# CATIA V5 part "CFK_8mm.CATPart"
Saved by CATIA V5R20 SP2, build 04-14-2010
Part number: CFK_8mm
Bounding box of the stored display mesh (mm): x -4 to 4, y -3.804 to 3.804, z 0 to 200
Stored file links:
  C:\Documents and Settings\Administrator\My Documents\Hobi_dokumenti\CAD_CNC\Clap_CATIA\CFK_8mm.CATPart
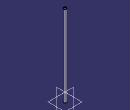
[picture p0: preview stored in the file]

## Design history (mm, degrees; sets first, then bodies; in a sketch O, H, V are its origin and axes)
Body1 (main body)
  Sketch1 on xy-plane, origin (0, 0, 0), H (1, 0, 0), V (0, 1, 0)
    circle A1 centre (0, 0) radius 3
    circle A2 centre (0, 0) radius 4
    radius A2 = 4
    radius A1 = 3
  Pad1: profile Sketch1, direction (0, 0, 1), length 200
  Chamfer1: length 0.2, angle 45, on edge [face of Pad1 from Sketch1.A2 | end face of Pad1]; edge [end face of Pad1 | face of Pad1 from Sketch1.A1]; start face of Pad1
